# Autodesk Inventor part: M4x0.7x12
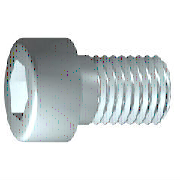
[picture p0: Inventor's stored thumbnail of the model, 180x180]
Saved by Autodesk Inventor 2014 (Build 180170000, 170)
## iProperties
IsCustomPart: 0
Created: 2016-05
Part Number: M4x0.7x12
Material: 강, 연강
Description: 6각머리 태핑 나사
Document SubType Name: Modeling
Standard: KS B 1003
Designer: mduedu
Standards Organization: KS
Language: ko-KR
Size Designation: M 4 x 12
Categories: <MemberInstance><Categories><Category DisplayName="조임쇠" InternalName="e4da775c-781d-43d5-af7c-5136215cf5a6" Mnemonic="FSTN"><Category DisplayName="볼트" InternalN
Density: 1 g/cm^3
Appearance: 연마 - 진회색
Author: mduedu
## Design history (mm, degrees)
sketch "스케치1"
  geometry: L1 (-1, 0)-(12, 0); L2 (12, 0)-(12, 2); L3 (12, 2)-(1.75, 2); L4 (1.75, 2)-(1.32, 2); L5 (1.32, 2)-(0, 2); L6 (0, 2)-(0, 3.5); L7 (0, 3.5)-(-4, 3.5); L8 (-4, 3.5)-(-4, 1.732); L9 (-4, 1.732)-(-2, 1.732); L10 (-2, 1.732)-(-1, 0); L11 (-7.2, 0)-(15.2, 0) reference; L12 (0, -0.7)-(0, 4.2) reference; L13 (1.75, 2)-(0, 2)
  constraints: 22 end point, 6 parallel, 2 collinear, 2 perpendicular, 1 horizontal, 1 point on line
  dimensions: "d1" = 10.25 distance from line of L3.end L2 (= GEL); "d2" = 0.42952 distance of L4.end L3.end (computed from GAL); "d3" = 4 distance between parallel lines of L8 L6 (= KOH); "d4" = 2 distance of L8.end L9.end (= INTI); "d5" = 60 deg angle of L10 L1; "d6" = 4 diameter of L3 L1 (= GD); "d7" = 4 diameter of L5 L1 (= BDM); "d8" = 3.4641 diameter of L9 L1 (= 1.1547 x SW); "d9" = 7 diameter of L7 L1 (= KOD); "d26" = 12 distance between parallel lines of L12 L2 (= NLG)
revolve "본체" sketch "스케치1" stored, may be unused: angle "d10" = 90 deg
sketch "스케치2"
  geometry: L1 (0, -4.9)-(0, 4.9) reference; L2 (-4.9, 0)-(4.9, 0) reference; L3 (1.732, 0)-(0.866, -1.5); L4 (0.866, -1.5)-(-0.866, -1.5); L5 (-0.866, -1.5)-(-1.732, 0); L6 (-1.732, 0)-(-0.866, 1.5); L7 (-0.866, 1.5)-(0.866, 1.5); L8 (0.866, 1.5)-(1.732, 0); 2 further points
  constraints: 12 end point, 1 coincident, 1 horizontal alignment, 1 point on line, 12 other
extrude "슬롯" join sketch "스케치2" stored distance "d11" = 10; taper "d12" = 0 deg
workplane "Work Plane1"
fillet "Fillet2" dims "d30" = 0.1 (= R)
body "Solid1"
fillet "모깎기1" dims "d17" = 0.4 (= RR)
feature "스레드" dims "d13" = 10.25 (= GEL), "d14" = 0
chamfer "모따기1" distance "d15" = 0.42941 (= -0.5 x SPD + 0.5 x GD); stored, may be unused: second distance "d16" = 0.42941 (= GUL), angle "d27" = 45 deg
other parameters: "GD" = 4 (= NND) [user parameter; used in 2 equation terms], "NLG" = 12 [user parameter; used in 1 equation term], "GEL" = 10.25 [user parameter; used in 2 equation terms], "KOD" = 7 [user parameter; used in 1 equation term], "KOH" = 4 [user parameter; used in 1 equation term], "INTI" = 2 [user parameter; used in 1 equation term], "GAL" = 0.42941 (= 0.61345 x PTC) [user parameter; used in 1 equation term], "GUL" = 0.42941 (= 0.61345 x PTC) [user parameter; used in 1 equation term], "BDM" = 4 (= NND) [user parameter; used in 1 equation term], "SW" = 3 [user parameter; used in 2 equation terms], "RR" = 0.4 [user parameter; used in 1 equation term], "SPD" = 3.14117 (= NND - 1.2269 x PTC) [user parameter; used in 1 equation term], "d19" = 0, "d28" = 0, "d29" = 0, "R" = 0.1 [user parameter; used in 1 equation term], "PHH" = 0.2 [user parameter], "GD1" = 3.14117 (= THREADDIA - 1.2269 x PTC) [user parameter], "THREADDIA" = 4 [user parameter; used in 1 equation term], "FAWI" = 45 deg [user parameter], "TPU" = 14.28571 (computed from PTC) [user parameter], "PTC" = 0.7 [user parameter; used in 5 equation terms], "NND" = 4 [user parameter; used in 3 equation terms], "TOA" = 30 deg [user parameter], "E0" = 3.465 (= 1.155 x SW) [user parameter]
